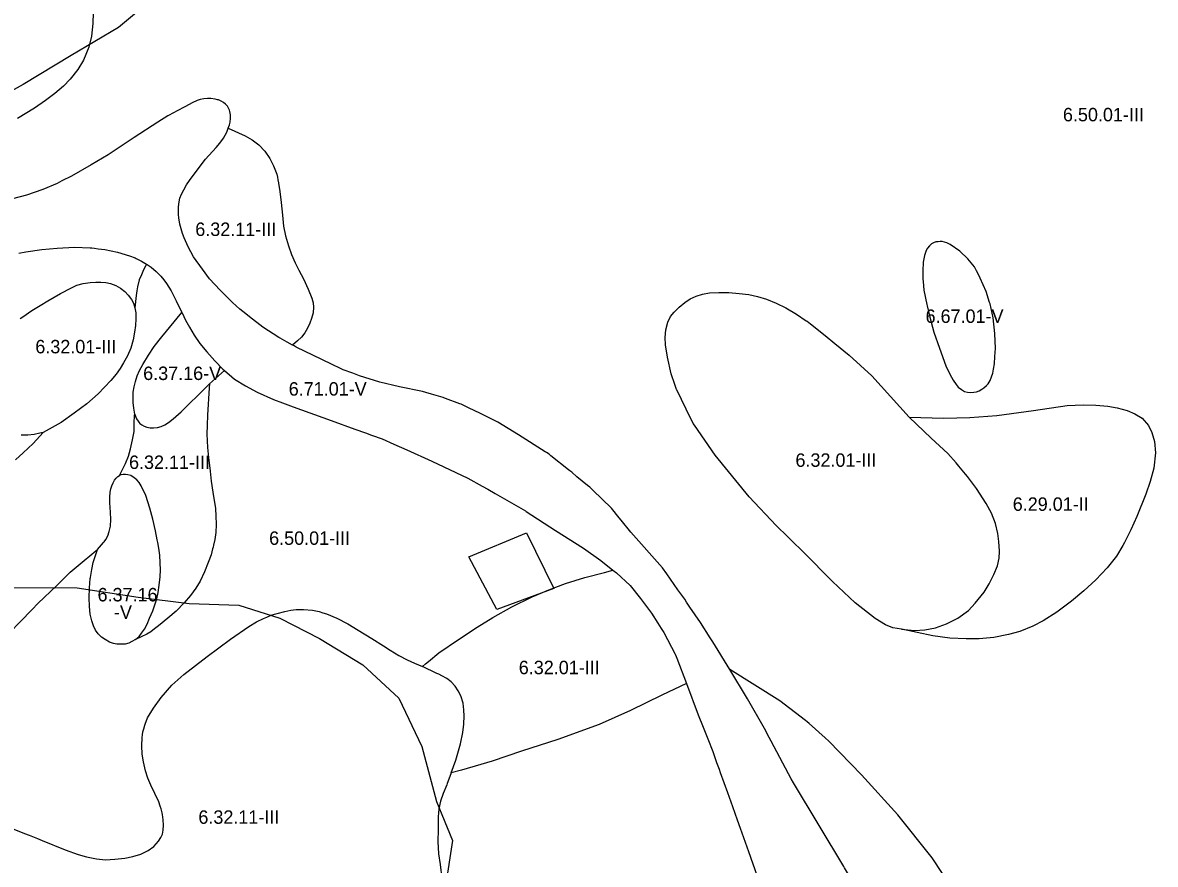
# Model space of a CAD drawing. Extents: x -555156 to -540209, y -1046851 to -1035695.
# Drawn here: x -542138 to -541296, y -1038823 to -1038196 of the extents above; entities that cross this region are included whole.
import ezdxf

# ---------------------------------------------------------------- set-up
doc = ezdxf.new("R2010")
doc.units = 0
for name, color, linetype in [('Vrstva 27', 7, 'Continuous'), ('Vrstva 28', 7, 'Continuous'), ('Vrstva 29', 7, 'Continuous')]:
    doc.layers.add(name, color=color, linetype=linetype)

msp = doc.modelspace()

# ---------------------------------------------------------------- linework, layer by layer
at = {"layer": 'Vrstva 28'}
for points in [[(-542085.84, -1038188.6), (-542085.99, -1038196.97), (-542087.04, -1038206.23), (-542088.98, -1038214.6), (-542093.01, -1038224.17), (-542097.34, -1038231.19), (-542103.02, -1038238.36), (-542107.95, -1038243.44), (-542114.37, -1038248.97), (-542121.24, -1038254.2), (-542129.46, -1038259.88), (-542142.15, -1038267.53)], [(-541985.32, -1038274.88), (-541984.38, -1038272.29), (-541983.89, -1038270.34), (-541983.65, -1038267.27), (-541983.67, -1038266.75), (-541983.74, -1038264.92), (-541984.13, -1038262.43), (-541984.52, -1038261.35), (-541984.86, -1038260.39), (-541986.04, -1038258.48), (-541987.3, -1038257.02), (-541987.48, -1038256.87), (-541988.82, -1038255.75), (-541990.62, -1038254.68), (-541992.67, -1038253.8), (-541993.43, -1038253.62), (-541995.16, -1038253.21), (-541998.23, -1038252.82), (-542000.5, -1038252.74), (-542000.91, -1038252.72), (-542003.64, -1038252.97), (-542006.13, -1038253.46), (-542008.42, -1038254.29), (-542012.08, -1038255.91), (-542017.12, -1038258.64), (-542023.94, -1038262.14), (-542025.68, -1038263.12), (-542030.18, -1038265.64), (-542037.71, -1038270.28), (-542055.33, -1038281.63), (-542074.68, -1038294.52), (-542087.37, -1038302.15), (-542102.01, -1038310.52), (-542109.01, -1038314.07), (-542112.62, -1038315.9), (-542123.22, -1038320.53), (-542135.47, -1038324.71), (-542145.93, -1038327.4)], [(-541937.52, -1038436.18), (-541941.66, -1038433.91), (-541946.87, -1038431.04), (-541947.68, -1038430.52), (-541959.6, -1038422.86), (-541969.5, -1038415.25), (-541972.4, -1038412.9), (-541976.76, -1038409.36), (-541982.16, -1038404.58), (-541985.77, -1038400.97), (-541991.42, -1038395.31), (-541999.34, -1038386.94), (-542004.56, -1038379.77), (-542011.28, -1038370.65), (-542015.2, -1038363), (-542018.1, -1038356.42), (-542019.28, -1038353.21), (-542019.89, -1038351.55), (-542021.26, -1038346.34), (-542022.2, -1038341.56), (-542022.21, -1038341.25), (-542022.29, -1038339.26), (-542022.36, -1038337.3), (-542022.39, -1038336.61), (-542022.47, -1038333.2), (-542021.96, -1038329.61), (-542021.36, -1038326.88), (-542020.25, -1038323.97), (-542018.46, -1038320.56), (-542016.33, -1038317.06), (-542014.2, -1038313.8), (-542007.7, -1038305.06), (-542002.17, -1038297.88), (-541994.29, -1038289.27), (-541991.56, -1038286.01), (-541991.05, -1038285.32), (-541989.41, -1038283.08), (-541988.89, -1038282.22), (-541987.56, -1038280.05), (-541986.54, -1038277.86), (-541985.32, -1038274.88)], [(-541985.32, -1038274.88), (-541972.72, -1038280.42), (-541967.49, -1038283.41), (-541962.71, -1038287.14), (-541958.23, -1038291.93), (-541954.35, -1038297.31), (-541951.81, -1038302.69), (-541949.27, -1038308.96), (-541948.8, -1038311.33), (-541948.44, -1038313.14), (-541947.98, -1038315.45), (-541947.93, -1038315.69), (-541947.03, -1038321.97), (-541945.98, -1038330.04), (-541945.09, -1038339.6), (-541944.34, -1038347.67), (-541942.75, -1038354.9), (-541940.66, -1038362.22), (-541938.27, -1038368.8), (-541935.58, -1038375.08), (-541932.75, -1038380.46), (-541929.31, -1038386.88), (-541925.88, -1038394.65), (-541923.11, -1038401.35), (-541922.26, -1038404.77), (-541921.92, -1038408.01), (-541922.17, -1038412.2), (-541923.35, -1038416.3), (-541923.37, -1038416.38), (-541924.65, -1038419.97), (-541926.36, -1038423.64), (-541928.49, -1038427.06), (-541930.88, -1038430.22), (-541933.78, -1038433.12)], [(-542141.09, -1038367.77), (-542135.95, -1038366.89), (-542124, -1038365.1), (-542112.5, -1038364.05), (-542099.8, -1038363.3), (-542088, -1038363.75), (-542086.72, -1038363.91), (-542084.75, -1038364.16), (-542082.13, -1038364.49), (-542077.25, -1038365.1), (-542067.69, -1038367.04), (-542058.88, -1038369.73), (-542054.7, -1038371.39), (-542053.76, -1038371.76), (-542049.83, -1038373.72), (-542046.19, -1038375.92)], [(-541430.93, -1038471.25), (-541428.88, -1038470.91), (-541426.84, -1038470.13), (-541424.93, -1038469.06), (-541423.42, -1038468.13), (-541421.37, -1038466.37), (-541420.11, -1038464.91), (-541418.74, -1038462.47), (-541417.62, -1038459.79), (-541416.74, -1038457.15), (-541416.18, -1038454.24), (-541415.58, -1038450.14), (-541415.16, -1038444.76), (-541414.78, -1038438.74), (-541415.23, -1038427.68), (-541416.43, -1038415.87), (-541418.82, -1038405.41), (-541419.11, -1038404.5), (-541421.66, -1038396.44), (-541426.14, -1038386.28), (-541426.94, -1038384.68), (-541428.85, -1038380.86), (-541430.32, -1038377.91), (-541435.25, -1038371.93), (-541441.22, -1038366.4), (-541448.54, -1038361.32), (-541449.51, -1038360.8), (-541451.07, -1038360.15), (-541452.69, -1038359.57), (-541454.42, -1038359.23), (-541454.83, -1038359.2), (-541456.01, -1038359.12), (-541457.51, -1038359.26), (-541458.29, -1038359.36), (-541459.24, -1038359.48), (-541460.88, -1038360.04), (-541462.28, -1038360.85), (-541463.81, -1038362.33), (-541465.26, -1038364.17), (-541466.23, -1038365.79), (-541466.9, -1038367.29), (-541467.54, -1038369.59), (-541468.48, -1038374.54), (-541468.82, -1038381.03), (-541468.82, -1038385.46), (-541468.82, -1038387.1), (-541468.64, -1038388.93), (-541468.01, -1038395.45)], [(-542046.19, -1038375.92), (-542046.92, -1038377.36), (-542048.36, -1038380.2), (-542050, -1038383.94), (-542051.5, -1038387.68)], [(-542046.19, -1038375.92), (-542045.73, -1038376.2), (-542042.75, -1038378.25), (-542038.99, -1038381.32), (-542035.58, -1038384.91), (-542033.37, -1038387.76), (-542031.4, -1038390.29), (-542027.9, -1038395.76), (-542024.06, -1038403.36), (-542019.78, -1038411.89)], [(-542140.07, -1038416.4), (-542138.12, -1038415.07), (-542131.56, -1038410.57), (-542125.24, -1038406.7), (-542119.61, -1038403.25), (-542110.05, -1038397.87), (-542101.98, -1038393.56), (-542098.06, -1038391.68), (-542093.19, -1038390.31), (-542088.07, -1038389.72), (-542083.89, -1038389.29), (-542080.22, -1038389.29), (-542076.46, -1038389.63), (-542072.96, -1038390.31), (-542069.04, -1038391.94), (-542065.45, -1038393.9), (-542062.38, -1038396.29), (-542059.82, -1038398.94), (-542057.34, -1038402.27), (-542055.89, -1038405.09), (-542054.87, -1038408.42)], [(-542051.5, -1038387.68), (-542052.84, -1038392.76), (-542053.34, -1038395.84), (-542053.89, -1038399.18), (-542054.87, -1038408.42)], [(-541484.57, -1038647.71), (-541491, -1038646.51), (-541496.67, -1038644.27), (-541504.29, -1038639.64), (-541519, -1038628.09), (-541535.86, -1038612.21), (-541557.82, -1038589.98), (-541566.48, -1038581.53), (-541569.1, -1038578.98), (-541577.95, -1038570.36), (-541598.07, -1038549.18), (-541623.17, -1038518.05), (-541638.67, -1038495.9), (-541639.64, -1038494.51), (-541644.71, -1038483.8), (-541651.66, -1038469.62), (-541651.88, -1038469.16), (-541653.22, -1038465.44), (-541656.07, -1038457.5), (-541658.61, -1038445.24), (-541660.1, -1038436.13), (-541660.4, -1038430.45), (-541659.95, -1038424.77), (-541658.46, -1038419.09), (-541656.36, -1038415.05), (-541653.68, -1038411.77), (-541649.94, -1038407.88), (-541645.91, -1038404.59), (-541641.73, -1038401.9), (-541637.25, -1038399.81), (-541632.62, -1038398.32), (-541627.54, -1038397.42), (-541620.52, -1038397.12), (-541613.05, -1038396.97), (-541605.43, -1038397.72)], [(-541605.43, -1038397.72), (-541598.26, -1038398.61), (-541591.84, -1038399.96), (-541585.12, -1038402.05), (-541577.8, -1038405.04), (-541570.63, -1038408.48), (-541562.71, -1038413.11), (-541555.48, -1038418.04), (-541554.87, -1038418.45), (-541552.35, -1038420.48), (-541541.54, -1038429.18), (-541534.3, -1038435.01), (-541523.57, -1038443.63), (-541506.84, -1038459.06), (-541478.87, -1038489.92)], [(-541468.01, -1038395.45), (-541465.87, -1038406.04), (-541465.63, -1038407.06), (-541463.65, -1038415.35), (-541460.5, -1038426.54), (-541456.4, -1038438.49), (-541451.66, -1038451.73), (-541448.83, -1038457.79), (-541446.35, -1038462.18), (-541444.05, -1038465.5), (-541442.44, -1038467.45), (-541439.96, -1038469.35), (-541437.81, -1038470.62), (-541435.47, -1038471.25), (-541433.23, -1038471.45), (-541430.93, -1038471.25)], [(-542054.87, -1038408.42), (-542054.19, -1038412.26), (-542054.02, -1038416.62), (-542054.44, -1038421.66), (-542055.09, -1038426.52), (-542056.2, -1038432.33), (-542057.91, -1038438.56), (-542060.3, -1038444.12), (-542063.29, -1038449.32), (-542065.76, -1038453.51), (-542068.84, -1038457.95), (-542072.8, -1038462.65), (-542082.06, -1038472.36), (-542090.58, -1038479.84), (-542099.84, -1038486.86), (-542109.54, -1038493.73), (-542123.03, -1038501.32)], [(-542054.96, -1038487.5), (-542055.55, -1038483.23), (-542055.98, -1038479.04), (-542056.15, -1038475.28), (-542055.98, -1038471.19), (-542055.38, -1038467.17), (-542054.44, -1038463.33), (-542053.08, -1038459.14), (-542051.37, -1038455.22), (-542048.98, -1038450.69), (-542044.63, -1038443.77), (-542040.36, -1038437.37), (-542034.73, -1038430.02), (-542019.92, -1038412.06), (-542019.78, -1038411.89)], [(-542019.78, -1038411.89), (-542019.65, -1038412.17), (-542017.09, -1038417.57), (-542014.26, -1038422.95), (-542010.67, -1038428.93), (-542006.49, -1038434.91), (-542001.41, -1038441.33), (-541995.44, -1038447.91), (-541989.3, -1038454.18), (-541988.27, -1038455.23)], [(-541933.78, -1038433.12), (-541937.52, -1038436.18)], [(-541612.42, -1038677.5), (-541624.96, -1038657.1), (-541626.87, -1038654.1), (-541634.11, -1038642.71), (-541641.97, -1038631.16), (-541644.51, -1038627.42), (-541645.91, -1038625.37), (-541650.92, -1038618.21), (-541659.18, -1038606.41), (-541662.38, -1038601.84), (-541685.9, -1038575.42), (-541693.05, -1038566.58), (-541694.57, -1038564.69), (-541700.28, -1038557.64), (-541714.14, -1038544.04), (-541716.54, -1038542.04), (-541718.17, -1038540.68), (-541726.01, -1038534.14), (-541729.92, -1038530.88), (-541731.39, -1038529.65), (-541732.3, -1038528.93), (-541745.37, -1038518.51), (-541746.81, -1038517.36), (-541748.77, -1038516.12), (-541749.57, -1038515.61), (-541769.53, -1038502.98), (-541784.77, -1038493.57), (-541798.36, -1038486.84), (-541806.28, -1038483.05), (-541812.1, -1038480.27), (-541813.13, -1038479.88), (-541823.86, -1038475.83), (-541825.55, -1038475.19), (-541834.29, -1038472.61), (-541838.32, -1038471.42), (-541840.78, -1038470.7), (-541857.96, -1038467.27), (-541872.75, -1038463.83), (-541887.83, -1038459.05), (-541892.72, -1038457.2), (-541899.82, -1038454.51), (-541901.91, -1038453.53), (-541908.06, -1038450.65), (-541915.8, -1038447.03), (-541934.73, -1038437.63), (-541936.26, -1038436.87), (-541937.52, -1038436.18)], [(-541988.27, -1038455.23), (-541999.31, -1038465.09)], [(-541988.27, -1038455.23), (-541982.71, -1038459.81), (-541980.65, -1038461.51), (-541972.58, -1038466.59), (-541963.77, -1038471.22), (-541951.82, -1038476.75), (-541945.08, -1038479.2), (-541937.03, -1038482.13), (-541908.8, -1038492.3), (-541891.13, -1038498.67), (-541883.41, -1038501.48), (-541878.92, -1038503.11), (-541871, -1038505.99), (-541862.15, -1038509.86), (-541852.44, -1038514.1), (-541833.88, -1038522.47), (-541807.22, -1038535.28), (-541796.57, -1038541.16), (-541792.42, -1038543.45), (-541786.83, -1038546.53), (-541764.35, -1038559.6), (-541763.86, -1038559.92), (-541741.87, -1038574.25), (-541721.22, -1038587.33), (-541708.38, -1038596.37), (-541699.29, -1038603.72)], [(-542038.04, -1038497.47), (-542035.36, -1038496.79), (-542032.53, -1038495.52), (-542029.89, -1038493.86), (-542026.38, -1038491.13), (-542020.48, -1038485.85), (-542014.07, -1038479.7), (-542007.93, -1038473.72), (-542004.72, -1038470.43), (-542004.26, -1038469.96), (-541999.31, -1038465.09)], [(-541999.31, -1038465.09), (-541999.5, -1038467.91), (-542000.84, -1038488.4), (-542001.14, -1038495.87)], [(-541478.87, -1038489.92), (-541453.14, -1038490.61), (-541433.79, -1038490.09), (-541413.67, -1038488.52), (-541386.48, -1038484.85), (-541361.39, -1038481.19), (-541349.65, -1038480.7), (-541340.24, -1038481), (-541331.28, -1038481.59), (-541324.26, -1038482.94), (-541316.94, -1038484.88), (-541311.12, -1038487.27), (-541305.74, -1038490.56)], [(-542066.35, -1038533.29), (-542061.83, -1038524.26), (-542059.59, -1038518.88), (-542058.09, -1038513.35), (-542056.45, -1038506.63), (-542055.4, -1038500.5), (-542055.27, -1038495.33), (-542055.25, -1038494.67), (-542054.98, -1038488.06), (-542054.96, -1038487.5)], [(-542054.96, -1038487.5), (-542054.77, -1038487.96), (-542053.5, -1038491.03), (-542052.47, -1038492.84), (-542051.84, -1038493.61), (-542051.16, -1038494.45), (-542049.69, -1038495.62), (-542047.94, -1038496.55), (-542045.79, -1038497.23), (-542043.45, -1038497.67), (-542040.96, -1038497.77), (-542038.04, -1038497.47)], [(-541305.74, -1038490.56), (-541300.96, -1038495.94), (-541298.42, -1038501.17), (-541296.63, -1038507.9), (-541295.88, -1038516.42), (-541297.08, -1038527.77), (-541299.76, -1038537.79), (-541302.9, -1038547.2), (-541309.62, -1038563.79), (-541314.01, -1038573.59), (-541314.82, -1038575.16), (-541316.92, -1038579.22), (-541318.93, -1038583.09), (-541320.13, -1038585.4), (-541324.76, -1038593.17), (-541331.64, -1038601.99), (-541340.15, -1038610.95), (-541348.96, -1038619.02), (-541358.22, -1038626.79), (-541369.13, -1038635.01), (-541379.28, -1038641.44), (-541386.9, -1038645.48), (-541396.76, -1038649.36), (-541405.12, -1038651.6), (-541416.03, -1038653.69), (-541426.93, -1038654.89), (-541436.64, -1038654.89), (-541448.74, -1038654.29), (-541461.29, -1038652.5), (-541484.57, -1038647.71)], [(-541467.25, -1038648.16), (-541459.48, -1038646.51), (-541451.26, -1038643.53), (-541442.75, -1038639.49), (-541434.83, -1038633.66), (-541429.94, -1038628.32), (-541423.22, -1038619.95), (-541419.49, -1038613.97), (-541415.9, -1038606.95), (-541413.36, -1038600.52), (-541412.02, -1038594.69), (-541411.72, -1038589.46), (-541412.17, -1038582.29), (-541412.91, -1038576.31), (-541414.71, -1038568.99), (-541417.84, -1038561.37), (-541421.58, -1038554.04), (-541428.9, -1038542.98), (-541435.62, -1038534.02), (-541437.04, -1038532.31), (-541439.54, -1038529.27), (-541442.04, -1038526.24), (-541444.08, -1038523.87), (-541450.11, -1038516.86), (-541462.66, -1038505.35), (-541478.87, -1038489.92)], [(-542001.14, -1038495.87), (-542001.29, -1038502.45), (-542000.84, -1038512.46), (-542000.09, -1038519.78), (-541998.9, -1038530.1), (-541998, -1038537.42), (-541996.81, -1038545.64), (-541994.91, -1038557.8), (-541994.87, -1038558.04), (-541994.57, -1038563.33), (-541994.27, -1038569.61), (-541994.57, -1038575.73), (-541995.31, -1038580.97), (-541996.28, -1038585.03), (-541996.66, -1038586.64), (-541996.96, -1038587.76), (-541998.15, -1038592.17), (-542000.39, -1038598), (-542003.08, -1038604.88), (-542006.37, -1038611.75), (-542009.36, -1038617.13), (-542013.39, -1038622.51), (-542018.17, -1038628.04), (-542024.14, -1038634.17), (-542030.27, -1038639.4), (-542037.14, -1038645.08), (-542040.15, -1038647.46), (-542042.84, -1038649.51), (-542045.81, -1038651.22), (-542050.25, -1038653.37), (-542054.35, -1038655.19)], [(-542123.03, -1038501.32), (-542130.49, -1038509.39), (-542137.81, -1038516.41), (-542143.64, -1038521.64)], [(-542134.38, -1038503.11), (-542139.26, -1038503.35)], [(-542123.03, -1038501.32), (-542125.46, -1038501.79), (-542129.6, -1038502.62), (-542134.38, -1038503.11)], [(-542082.67, -1038588.19), (-542078.04, -1038583.11), (-542077.59, -1038582.51), (-542076.44, -1038580.99), (-542074.9, -1038578.26), (-542073.96, -1038575.01), (-542073.03, -1038570.91), (-542072.77, -1038565.96), (-542073.05, -1038560.52), (-542073.47, -1038553.68), (-542073.47, -1038549.41), (-542073.28, -1038545.68), (-542072.79, -1038543.1), (-542072.01, -1038540.9), (-542070.94, -1038538.61), (-542069.91, -1038536.75), (-542068.79, -1038535.24), (-542067.57, -1038534.07), (-542066.35, -1038533.29)], [(-542054.35, -1038655.19), (-542051.72, -1038652.94), (-542049.77, -1038650.65), (-542047.67, -1038647.48), (-542045.75, -1038643.78), (-542043.88, -1038639.51), (-542041.57, -1038633.96), (-542039.86, -1038629.43), (-542038.41, -1038624.91), (-542037.43, -1038620.38), (-542036.75, -1038614.91), (-542035.98, -1038608.6), (-542035.81, -1038603.56), (-542035.83, -1038602.52), (-542035.88, -1038599.22), (-542035.9, -1038598.26), (-542036.32, -1038592.54), (-542037.01, -1038587.42), (-542037.74, -1038583.05), (-542038.12, -1038581.06), (-542039.38, -1038574.53), (-542041.48, -1038565.71), (-542043.57, -1038557.49), (-542046.55, -1038548.08), (-542050.01, -1038541.05), (-542051.53, -1038538.56), (-542053.23, -1038536.56), (-542055.28, -1038534.9), (-542057.82, -1038533.34), (-542059.96, -1038532.75), (-542061.87, -1038532.46), (-542063.52, -1038532.51), (-542065.18, -1038532.8), (-542066.35, -1038533.29)], [(-542126.79, -1038628.35), (-542113.03, -1038615.32), (-542111.75, -1038614.11), (-542110.8, -1038613.16), (-542102.93, -1038605.29), (-542093.97, -1038597.67), (-542086.7, -1038591.78), (-542084.99, -1038590.26), (-542082.67, -1038588.19)], [(-542064.93, -1038658.75), (-542068.2, -1038658.75), (-542070.74, -1038658.26), (-542073.62, -1038657.14), (-542076.93, -1038655.28), (-542079.62, -1038653.48), (-542082.15, -1038651.14), (-542084.1, -1038648.45), (-542085.61, -1038645.04), (-542086.88, -1038641.33), (-542088, -1038636.55), (-542088.57, -1038630.76), (-542088.74, -1038624.27), (-542088.65, -1038616.75), (-542087.97, -1038609.95), (-542087.89, -1038609.15), (-542086.86, -1038603.17), (-542085.75, -1038598.05), (-542083.41, -1038590.57), (-542082.67, -1038588.19)], [(-541774.35, -1038631.03), (-541759.26, -1038623.56), (-541747.01, -1038618.33), (-541734.47, -1038613.7), (-541720.13, -1038609.06), (-541705.64, -1038605.33), (-541699.29, -1038603.72)], [(-541699.29, -1038603.72), (-541696.73, -1038605.79), (-541686.57, -1038615.2), (-541678.81, -1038624.77), (-541670.59, -1038635.68), (-541665.82, -1038643.07), (-541663.28, -1038647), (-541661.33, -1038650.02), (-541652.97, -1038666.16), (-541652.8, -1038666.59), (-541651.86, -1038669.08), (-541644.6, -1038688.13)], [(-542200.33, -1038668.82), (-542184.9, -1038665.86), (-542173.55, -1038663.32), (-542166.23, -1038661.08), (-542159.06, -1038657.79), (-542153.68, -1038654.65), (-542148.01, -1038650.32), (-542139.79, -1038641.95), (-542131.45, -1038633.22), (-542126.79, -1038628.35)], [(-542193.74, -1038776.8), (-542136.9, -1038799.53), (-542133.38, -1038800.94), (-542127.22, -1038803.41), (-542123.76, -1038804.79), (-542106.58, -1038811.81), (-542097.02, -1038815.25), (-542090.75, -1038816.89), (-542083.28, -1038818.53), (-542076.56, -1038819.13), (-542069.69, -1038818.83), (-542062.22, -1038817.94), (-542056.24, -1038816.74), (-542050.27, -1038814.95), (-542044.89, -1038812.41), (-542040.71, -1038809.27), (-542037.12, -1038805.23), (-542035.57, -1038802.67), (-542034.37, -1038800.11), (-542033.77, -1038797.21), (-542033.52, -1038793.45), (-542033.69, -1038789.35), (-542034.2, -1038785.51), (-542034.51, -1038784.2), (-542035.23, -1038781.24), (-542035.9, -1038779.33), (-542037.02, -1038776.11), (-542042.83, -1038763.72), (-542045.18, -1038758.45), (-542046.83, -1038753.07), (-542048.47, -1038746.35), (-542049.37, -1038740.67), (-542049.66, -1038734.39), (-542049.37, -1038728.27), (-542049.08, -1038726.23), (-542048.77, -1038724.08), (-542048.13, -1038721.67), (-542047.42, -1038719), (-542047.11, -1038718.17), (-542045.33, -1038713.47), (-542041, -1038706.3), (-542035.18, -1038698.53), (-542027.26, -1038689.26), (-542018.32, -1038681.26), (-542001.14, -1038667.96), (-541983.66, -1038655.11), (-541970.07, -1038645.69), (-541964.26, -1038642.16), (-541959.13, -1038639.6), (-541956.55, -1038638.54), (-541953.5, -1038637.29), (-541951.05, -1038636.49), (-541949.06, -1038635.84), (-541943.26, -1038634.39), (-541938.73, -1038633.45), (-541934.85, -1038632.96), (-541933.95, -1038632.85), (-541933.86, -1038632.85), (-541929.52, -1038632.94), (-541922.69, -1038633.54), (-541917.74, -1038634.56), (-541915.03, -1038635.41), (-541912.27, -1038636.27), (-541904.68, -1038639.51), (-541896.48, -1038643.7), (-541888.63, -1038648.22), (-541878.65, -1038654.46), (-541869.85, -1038660.1), (-541864.91, -1038663.32), (-541858.43, -1038667.08), (-541852.2, -1038670.41), (-541846.73, -1038672.97), (-541841.02, -1038675.37)], [(-541841.02, -1038675.37), (-541838.66, -1038673.43), (-541836.49, -1038671.64), (-541828.72, -1038665.26), (-541814.23, -1038655.24), (-541800.19, -1038645.98), (-541788.69, -1038638.8), (-541774.35, -1038631.03)], [(-541484.57, -1038647.71), (-541475.01, -1038648.61), (-541467.25, -1038648.16)], [(-542054.35, -1038655.19), (-542056.98, -1038656.75), (-542059.42, -1038657.97), (-542062.11, -1038658.65), (-542064.93, -1038658.75)], [(-541819.48, -1038754.6), (-541816.19, -1038745.19), (-541812.76, -1038732.93), (-541810.89, -1038724.56), (-541810.15, -1038718.19), (-541810.12, -1038717.9), (-541809.95, -1038712.69), (-541809.96, -1038712.33), (-541810.12, -1038707.65), (-541810.72, -1038702.61), (-541812.42, -1038697.31), (-541814.3, -1038693.47), (-541816.6, -1038690.05), (-541819.68, -1038686.9), (-541822.92, -1038684.42), (-541826.59, -1038682.2), (-541828.78, -1038681.16), (-541830.18, -1038680.49), (-541834.68, -1038678.36), (-541836.49, -1038677.5), (-541841.02, -1038675.37)], [(-541380.04, -1039082.96), (-541381.79, -1039079.78), (-541401.05, -1039044.89), (-541404.1, -1039039.37), (-541435.69, -1038982.14), (-541438.3, -1038977.41), (-541440.84, -1038972.81), (-541451.59, -1038953.35), (-541488.19, -1038891.57), (-541490.98, -1038886.8), (-541524.83, -1038828.9), (-541527.04, -1038825.13), (-541527.53, -1038824.28), (-541564.9, -1038761.93), (-541566.67, -1038758.97), (-541568.59, -1038755.36), (-541581.53, -1038730.99), (-541583.02, -1038728.19), (-541586.54, -1038721.57), (-541599.08, -1038699.34), (-541612.42, -1038677.5)], [(-541447.04, -1038840.25), (-541461.88, -1038817.68), (-541487.5, -1038785.64), (-541514.29, -1038756.1), (-541538.6, -1038730.99), (-541541.54, -1038728.38), (-541553.37, -1038717.89), (-541554.81, -1038716.61), (-541556.16, -1038715.57), (-541575.2, -1038700.92), (-541612.42, -1038677.5)], [(-541644.6, -1038688.13), (-541662.96, -1038696.71), (-541686.22, -1038708.22), (-541709.48, -1038718.42), (-541740.33, -1038729.67), (-541767.25, -1038738.3), (-541789.21, -1038745.88), (-541797.63, -1038748.31), (-541811.86, -1038752.41)], [(-541644.6, -1038688.13), (-541635.81, -1038711.32), (-541632.16, -1038720.57), (-541628.77, -1038729.17), (-541625.09, -1038738.52), (-541622.16, -1038746.7), (-541620.35, -1038751.74), (-541619.43, -1038754.3), (-541614.12, -1038769.12), (-541610.35, -1038779.64), (-541606.8, -1038789.52), (-541604.58, -1038795.77), (-541598.43, -1038813.06)], [(-541811.86, -1038752.41), (-541819.48, -1038754.6)], [(-541819.48, -1038754.6), (-541820.51, -1038757.27), (-541822.47, -1038762.37), (-541822.92, -1038763.52), (-541825.43, -1038769.85), (-541827.52, -1038775.53), (-541828.71, -1038781.36), (-541829.16, -1038787.34), (-541829.16, -1038796.61), (-541829.61, -1038805.57), (-541829.01, -1038814.69)], [(-541829.01, -1038814.69), (-541827.82, -1038822.61), (-541826.47, -1038833.22), (-541824.99, -1038841.09), (-541822.75, -1038849.01), (-541821.92, -1038851.4), (-541820.47, -1038855.59), (-541820.06, -1038856.78)], [(-541598.43, -1038813.06), (-541591.9, -1038831.36)]]:
    msp.add_lwpolyline(points, dxfattribs=at)
at = {"layer": 'Vrstva 29'}
for points in [[(-542029.986992, -1038168.774999), (-542066.966991, -1038199.901006), (-542102.211996, -1038220.752999), (-542137.8, -1038242.330001), (-542167.115992, -1038258.520004)], [(-541763.570007, -1038575.849976), (-541743.171021, -1038617.39801), (-541785.731018, -1038633.031006), (-541806.400024, -1038593.752014), (-541763.570007, -1038575.849976)], [(-542144.947999, -1038616.525994), (-542097.625008, -1038616.801008), (-542052.374005, -1038623.731), (-542014.545001, -1038628.497997), (-541977.588007, -1038629.837001), (-541946.980992, -1038639.366998), (-541917.569001, -1038654.635003), (-541885.324999, -1038674.074998), (-541858.597002, -1038698.992999), (-541841.354004, -1038734.796007), (-541830.606992, -1038775.704995), (-541818.701997, -1038804.734996), (-541823.790995, -1038838.897997), (-541850.582003, -1038855.389003), (-541893.826996, -1038872.474003), (-541934.449992, -1038869.675), (-542015.347995, -1038859.004998), (-542090.061992, -1038854.440997), (-542134.010001, -1038838.718006), (-542179.028999, -1038823.378996)]]:
    msp.add_lwpolyline(points, dxfattribs=at)

# ---------------------------------------------------------------- texts
at = {"layer": 'Vrstva 27'}
for s, p in [('6.50.01-III', (-541364.606548, -1038269.7)), ('6.32.11-III', (-542009.866548, -1038355)), ('6.67.01-V', (-541466.761006, -1038419.69)), ('6.32.01-III', (-542128.833926, -1038442.34)), ('6.37.16-V', (-542048.637974, -1038462.2)), ('6.71.01-V', (-541940.391006, -1038473.79)), ('6.32.01-III', (-541563.536548, -1038526.78)), ('6.32.11-III', (-542059.156548, -1038528.37)), ('6.29.01-II', (-541401.940312, -1038559.53)), ('6.50.01-III', (-541954.956548, -1038584.84)), ('6.37.16', (-542082.567329, -1038626.91)), ('-V', (-542070.354194, -1038639.91)), ('6.32.01-III', (-541769.306548, -1038681.1)), ('6.32.11-III', (-542007.576548, -1038792.42))]:
    msp.add_text(s, height=10, dxfattribs=at).set_placement(p)

doc.saveas('drawing.dxf')
